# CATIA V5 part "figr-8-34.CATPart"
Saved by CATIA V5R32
Part number: Part1
Bounding box of the stored display mesh (mm): x -75 to 75, y -75 to 75, z 0 to 20
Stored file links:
  D:\PROJECTS\Project 2022\CATIA V5 6R 2022\Resources\Part Files\c08_catia_v5_6r2022_prt\figr-8-34.CATPart
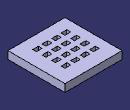
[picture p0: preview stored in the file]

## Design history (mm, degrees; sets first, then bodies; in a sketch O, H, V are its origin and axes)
Body1 (main body)
  Sketch1 on xy-plane, origin (0, 0, 0), H (1, 0, 0), V (0, 1, 0)
    line L1 (-75, 75) -> (75, 75)
    line L2 (75, 75) -> (75, -75)
    line L3 (75, -75) -> (-75, -75)
    line L4 (-75, -75) -> (-75, 75)
    axis line L5 (75, -75) -> (-75, 75)
    length L3 = 150
    length L2 = 150
    horizontal: L1 H, L3 H
    vertical: L2 V, L4 V
    midpoint: O L5
  Pad1: profile Sketch1, direction (0, 0, 1), length 20
  Sketch2 on face of Pad1, origin (0, 0, 20), H (1, 0, 0), V (0, 1, 0)
    line L1 (25, 40) -> (40, 40)
    line L2 (40, 40) -> (40, 30)
    line L3 (40, 30) -> (25, 30)
    line L4 (25, 30) -> (25, 40)
    reference projected line E1 (75, -75) -> (75, 75) from edge [face of Pad1 | face of Pad1]
    reference projected line E2 (75, 75) -> (-75, 75) from edge [face of Pad1 | face of Pad1]
    length L3 = 15
    length L4 = 10
    distance L2 E1 = 35
    distance L1 E2 = 35
    horizontal: L1 H, L3 H
    vertical: L2 V, L4 V
  Pocket1: profile Sketch2, direction (0, 0, -1), through (limit type 3)
  RectPattern1: of Pocket1, direction 1 instances 4, spacing 25, along end face of Pad1 reversed, direction 2 instances 4, spacing 25, along end face of Pad1 reversed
